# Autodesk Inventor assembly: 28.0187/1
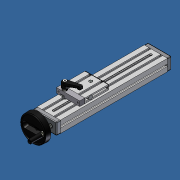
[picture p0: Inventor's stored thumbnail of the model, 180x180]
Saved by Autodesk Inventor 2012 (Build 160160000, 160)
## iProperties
Created: 2007-06
Part Number: 28.0187/1
Document SubType Name: Assembly
Designer: Andy Moles
Description: ADJUSTING UNIT VEN 45X90S WITH TOP CLAMP
Author: Andy Moles
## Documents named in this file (16)
- C:\Andys Backup Data\ANDY'S INVENTOR\INVENTOR LIBRARIES\PARTS LIBRARY\READY FOR USE MODULES LG\28.0187_1 ADJUSTING UNIT VEN 45X90S WITH TOP CLAMP.iam
- C:\Andys Backup Data\ANDY'S INVENTOR\INVENTOR LIBRARIES\PARTS LIBRARY\READY FOR USE MODULES LG\SUBCOMPONENTS\28.0200 BEARING PLATE 45X90 HANDWHEEL SIDE.ipt
- C:\Andys Backup Data\ANDY'S INVENTOR\INVENTOR LIBRARIES\PARTS LIBRARY\READY FOR USE MODULES LG\SUBCOMPONENTS\50.1264 BALL BEARING 10X30X9 6200 2RS DIN 625.ipt
- C:\Andys Backup Data\ANDY'S INVENTOR\INVENTOR LIBRARIES\PARTS LIBRARY\READY FOR USE MODULES LG\SUBCOMPONENTS\28.0201 BEARING PLATE 45X90 IDLER SIDE.ipt
- C:\Andys Backup Data\ANDY'S INVENTOR\INVENTOR LIBRARIES\PARTS LIBRARY\READY FOR USE MODULES LG\SUBCOMPONENTS\28.0204 HANDWHEEL 100mm.iam
- C:\Andys Backup Data\ANDY'S INVENTOR\INVENTOR LIBRARIES\PARTS LIBRARY\FASTENING ELEMENTS\SCREWS CAP\21.1204 M8X25.ipt
- C:\Andys Backup Data\ANDY'S INVENTOR\INVENTOR LIBRARIES\PARTS LIBRARY\READY FOR USE MODULES LG\SUBCOMPONENTS\28.0215_3 45x90F  PROFILE FOR TOP LOCK.ipt
- C:\Andys Backup Data\ANDY'S INVENTOR\INVENTOR LIBRARIES\PARTS LIBRARY\READY FOR USE MODULES LG\SUBCOMPONENTS\28.0221_1 ACME SCREW 16X4 TOP LOCK.ipt
- C:\Andys Backup Data\ANDY'S INVENTOR\INVENTOR LIBRARIES\PARTS LIBRARY\FASTENING ELEMENTS\WASHERS\21.1326 DISC SPRING 20.ipt
- C:\Andys Backup Data\ANDY'S INVENTOR\INVENTOR LIBRARIES\PARTS LIBRARY\FASTENING ELEMENTS\SCREWS COUNTERSUNK\21.1543 M5x12 CSUNK.ipt
- C:\Andys Backup Data\ANDY'S INVENTOR\INVENTOR LIBRARIES\PARTS LIBRARY\READY FOR USE MODULES LG\SUBCOMPONENTS\28.0258 Nut slide connector 35.5.ipt
- C:\Andys Backup Data\ANDY'S INVENTOR\INVENTOR LIBRARIES\PARTS LIBRARY\READY FOR USE MODULES LG\SUBCOMPONENTS\28.0257 BRONZE NUT 16X4 NOTCHED.ipt
- C:\Andys Backup Data\ANDY'S INVENTOR\INVENTOR LIBRARIES\PARTS LIBRARY\READY FOR USE MODULES LG\28.0280_9 SLIDE CLAMPING UNIT FOR SLIDE LWN-S.iam
- C:\Andys Backup Data\ANDY'S INVENTOR\INVENTOR LIBRARIES\PARTS LIBRARY\COMPONENTS LG\22.1096 SLIDE RAIL LN-S.iam
- C:\Andys Backup Data\ANDY'S INVENTOR\INVENTOR LIBRARIES\PARTS LIBRARY\END CAPS\22.1014_1 END CAP 90X19 GRAY.ipt
- C:\Andys Backup Data\ANDY'S INVENTOR\INVENTOR LIBRARIES\PARTS LIBRARY\READY FOR USE MODULES LG\SUBCOMPONENTS\28.0237_3 SLIDE LWN-S WITH TOP CLAMP 90X19.ipt
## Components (22 placed, 15 different names)
1. 28.0215_3 45x90F  PROFILE FOR TOP LOCK:1 — Mate:13, Mate:14, Flush:2, Flush:3, Mate:15, Flush:4, Flush:5, Flush:7, Mate:17, Flush:8, Mate:39, Angle:7, Flush:14
2. 28.0200 BEARING PLATE 45X90 HANDWHEEL SIDE:1 — Insert:4, Insert:6, Insert:7, Insert:11, Mate:14, Mate:15, Flush:4, Flush:5
3. 50.1264 10X30X9 6200 2RS DIN 625 BALL BEARING:1 — Insert:11
4. 50.1264 10X30X9 6200 2RS DIN 625 BALL BEARING:2 — Insert:10, Insert:14
5. 28.0201 BEARING PLATE 45X90 IDLER SIDE:1 — Insert:8, Insert:9, Insert:10, Flush:7, Mate:17, Flush:8
6. 28.0204 HANDWHEEL 100mm:1 [sub-assembly] — Insert:4, Angle:3
7. 21.1204  M8 x 25:1 — Insert:6
8. 21.1204  M8 x 25:2 — Insert:7
9. 21.1204  M8 x 25:3 — Insert:8
10. 21.1204  M8 x 25:4 — Insert:9
11. 28.0221_1 ACME SCREW 16X4 TOP LOCK:1 — Insert:12, Insert:13, Angle:3, Mate:28
12. 21.1326 DISC SPRING 20:1 — Insert:12
13. 21.1326 DISC SPRING 20:2 — Insert:13, Insert:14
14. 21.1543 M5x12 C'SUNK:1 — Insert:15
15. 21.1543 M5x12 C'SUNK:2 — Mate:30, Insert:16
16. 28.0258 Nut slide connector 35.5:1 — Mate:27, Mate:30, Mate:31, Mate:40
17. 28.0257 BRONZE NUT 16X4 NOTCHED:1 — Mate:27, Mate:28, Mate:31
18. 28.0237_3 SLIDE LWN-S WITH TOP CLAMP 90X19:1 — Mate:34, Mate:35, Angle:5, Mate:36, Mate:37, Angle:6, Mate:38, Flush:12, Flush:13, Angle:7, Insert:15, Insert:16, Flush:14, Mate:40, Mate:41, Mate:42, Flush:15
19. 28.0280_9 SLIDE CLAMPING UNIT FOR SLIDE LWN-S:1 [sub-assembly] — Mate:41, Mate:42, Flush:15
20. 22.1096 SLIDE RAIL LN-S:1 [sub-assembly] — Mate:36, Mate:37, Angle:6, Mate:39
21. 22.1096 SLIDE RAIL LN-S:2 [sub-assembly] — Mate:34, Mate:35, Angle:5
22. 22.1014_1 END CAP 90X19 GRAY:1 — Mate:38, Flush:12, Flush:13
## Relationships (43: Mate 17, Insert 12, Flush 10, Angle 4)
- Insert:4: 28.0200 BEARING PLATE 45X90 HANDWHEEL SIDE:1 ↔ 28.0204 HANDWHEEL 100mm:1
- Insert:6: 28.0200 BEARING PLATE 45X90 HANDWHEEL SIDE:1 ↔ 21.1204  M8 x 25:1
- Insert:7: 28.0200 BEARING PLATE 45X90 HANDWHEEL SIDE:1 ↔ 21.1204  M8 x 25:2
- Insert:8: 28.0201 BEARING PLATE 45X90 IDLER SIDE:1 ↔ 21.1204  M8 x 25:3
- Insert:9: 28.0201 BEARING PLATE 45X90 IDLER SIDE:1 ↔ 21.1204  M8 x 25:4
- Insert:10: 50.1264 10X30X9 6200 2RS DIN 625 BALL BEARING:2 ↔ 28.0201 BEARING PLATE 45X90 IDLER SIDE:1
- Insert:11: 28.0200 BEARING PLATE 45X90 HANDWHEEL SIDE:1 ↔ 50.1264 10X30X9 6200 2RS DIN 625 BALL BEARING:1
- Mate:13: 28.0215_3 45x90F  PROFILE FOR TOP LOCK:1
- Mate:14: 28.0215_3 45x90F  PROFILE FOR TOP LOCK:1 ↔ 28.0200 BEARING PLATE 45X90 HANDWHEEL SIDE:1
- Flush:2: 28.0215_3 45x90F  PROFILE FOR TOP LOCK:1
- Flush:3: 28.0215_3 45x90F  PROFILE FOR TOP LOCK:1
- Mate:15: 28.0215_3 45x90F  PROFILE FOR TOP LOCK:1 ↔ 28.0200 BEARING PLATE 45X90 HANDWHEEL SIDE:1
- Flush:4: 28.0215_3 45x90F  PROFILE FOR TOP LOCK:1 ↔ 28.0200 BEARING PLATE 45X90 HANDWHEEL SIDE:1
- Flush:5: 28.0215_3 45x90F  PROFILE FOR TOP LOCK:1 ↔ 28.0200 BEARING PLATE 45X90 HANDWHEEL SIDE:1
- Flush:7: 28.0215_3 45x90F  PROFILE FOR TOP LOCK:1 ↔ 28.0201 BEARING PLATE 45X90 IDLER SIDE:1
- Mate:17: 28.0215_3 45x90F  PROFILE FOR TOP LOCK:1 ↔ 28.0201 BEARING PLATE 45X90 IDLER SIDE:1
- Flush:8: 28.0215_3 45x90F  PROFILE FOR TOP LOCK:1 ↔ 28.0201 BEARING PLATE 45X90 IDLER SIDE:1
- Insert:12: 28.0221_1 ACME SCREW 16X4 TOP LOCK:1 ↔ 21.1326 DISC SPRING 20:1
- Insert:13: 28.0221_1 ACME SCREW 16X4 TOP LOCK:1 ↔ 21.1326 DISC SPRING 20:2
- Insert:14: 50.1264 10X30X9 6200 2RS DIN 625 BALL BEARING:2 ↔ 21.1326 DISC SPRING 20:2
- Angle:3: 28.0204 HANDWHEEL 100mm:1 ↔ 28.0221_1 ACME SCREW 16X4 TOP LOCK:1
- Mate:27: 28.0258 Nut slide connector 35.5:1 ↔ 28.0257 BRONZE NUT 16X4 NOTCHED:1
- Mate:28: 28.0221_1 ACME SCREW 16X4 TOP LOCK:1 ↔ 28.0257 BRONZE NUT 16X4 NOTCHED:1
- Mate:30: 21.1543 M5x12 C'SUNK:2 ↔ 28.0258 Nut slide connector 35.5:1
- Mate:31: 28.0258 Nut slide connector 35.5:1 ↔ 28.0257 BRONZE NUT 16X4 NOTCHED:1
- Mate:34: 28.0237_3 SLIDE LWN-S WITH TOP CLAMP 90X19:1 ↔ 22.1096 SLIDE RAIL LN-S:2
- Mate:35: 28.0237_3 SLIDE LWN-S WITH TOP CLAMP 90X19:1 ↔ 22.1096 SLIDE RAIL LN-S:2
- Angle:5: 28.0237_3 SLIDE LWN-S WITH TOP CLAMP 90X19:1 ↔ 22.1096 SLIDE RAIL LN-S:2
- Mate:36: 28.0237_3 SLIDE LWN-S WITH TOP CLAMP 90X19:1 ↔ 22.1096 SLIDE RAIL LN-S:1
- Mate:37: 28.0237_3 SLIDE LWN-S WITH TOP CLAMP 90X19:1 ↔ 22.1096 SLIDE RAIL LN-S:1
- Angle:6: 28.0237_3 SLIDE LWN-S WITH TOP CLAMP 90X19:1 ↔ 22.1096 SLIDE RAIL LN-S:1
- Mate:38: 28.0237_3 SLIDE LWN-S WITH TOP CLAMP 90X19:1 ↔ 22.1014_1 END CAP 90X19 GRAY:1
- Flush:12: 28.0237_3 SLIDE LWN-S WITH TOP CLAMP 90X19:1 ↔ 22.1014_1 END CAP 90X19 GRAY:1
- Flush:13: 28.0237_3 SLIDE LWN-S WITH TOP CLAMP 90X19:1 ↔ 22.1014_1 END CAP 90X19 GRAY:1
- Mate:39: 28.0215_3 45x90F  PROFILE FOR TOP LOCK:1 ↔ 22.1096 SLIDE RAIL LN-S:1
- Angle:7: 28.0215_3 45x90F  PROFILE FOR TOP LOCK:1 ↔ 28.0237_3 SLIDE LWN-S WITH TOP CLAMP 90X19:1
- Insert:15: 21.1543 M5x12 C'SUNK:1 ↔ 28.0237_3 SLIDE LWN-S WITH TOP CLAMP 90X19:1
- Insert:16: 21.1543 M5x12 C'SUNK:2 ↔ 28.0237_3 SLIDE LWN-S WITH TOP CLAMP 90X19:1
- Flush:14: 28.0215_3 45x90F  PROFILE FOR TOP LOCK:1 ↔ 28.0237_3 SLIDE LWN-S WITH TOP CLAMP 90X19:1
- Mate:40: 28.0258 Nut slide connector 35.5:1 ↔ 28.0237_3 SLIDE LWN-S WITH TOP CLAMP 90X19:1
- Mate:41: 28.0237_3 SLIDE LWN-S WITH TOP CLAMP 90X19:1 ↔ 28.0280_9 SLIDE CLAMPING UNIT FOR SLIDE LWN-S:1
- Mate:42: 28.0237_3 SLIDE LWN-S WITH TOP CLAMP 90X19:1 ↔ 28.0280_9 SLIDE CLAMPING UNIT FOR SLIDE LWN-S:1
- Flush:15: 28.0237_3 SLIDE LWN-S WITH TOP CLAMP 90X19:1 ↔ 28.0280_9 SLIDE CLAMPING UNIT FOR SLIDE LWN-S:1
